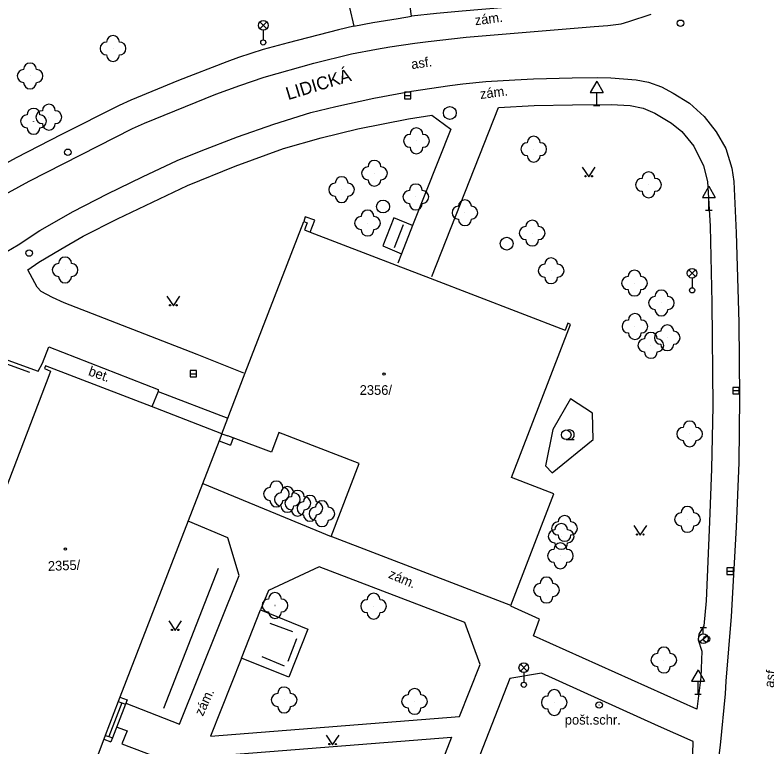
# Model space of a CAD drawing. Extents: x -737812 to -729375, y -1123000 to -1115500.
# Drawn here: x -736793.5 to -736735.1, y -1118373.1 to -1118316.3 of the extents above; entities that cross this region are included whole.
import ezdxf

# ---------------------------------------------------------------- set-up
doc = ezdxf.new("R2010")
doc.units = 0
for name, color, linetype in [('Doplněk polohopisu', 7, 'Continuous'), ('Doplňkové značky', 7, 'Continuous'), ('Hranice - ploty_ zdi', 7, 'Continuous'), ('Komunikace', 7, 'Continuous'), ('Názvy ulic_ silnic_ žel_', 7, 'Continuous'), ('Pomocné popisy', 7, 'Continuous'), ('Povr_ zn_ inž_ sítí - el_', 7, 'Continuous'), ('Povr_ zn_ inž_ sítí - kan_', 7, 'Continuous'), ('Povr_ zn_ inž_ sítí - vod_', 7, 'Continuous'), ('Stavební objekty', 7, 'Continuous'), ('Zeleň', 7, 'Continuous'), ('Značky druhů budov', 7, 'Continuous'), ('Značky druhů pozemků', 7, 'Continuous'), ('Čísla popisná', 7, 'Continuous')]:
    doc.layers.add(name, color=color, linetype=linetype)

msp = doc.modelspace()

# ---------------------------------------------------------------- linework, layer by layer
at = {"layer": 'Doplněk polohopisu'}
for p, q in [((-736763.36, -1118332.57), (-736764.06, -1118334.34)), ((-736762.64, -1118332.62), (-736763.5, -1118334.81)), ((-736782.39, -1118345.49), (-736776.98, -1118347.57)), ((-736778.92, -1118352.62), (-736768.95, -1118356.75)), ((-736775.92, -1118366.17), (-736774.44, -1118362.43)), ((-736773.71, -1118363.47), (-736771.94, -1118364.12)), ((-736771.64, -1118364.68), (-736772.31, -1118366.43)), ((-736772.58, -1118366.8), (-736774.31, -1118366.07))]:
    msp.add_line(p, q, dxfattribs=at)
for points in [[(-736744.93, -1118314.39), (-736745.88, -1118314.7), (-736746.86, -1118314.94), (-736758.79, -1118315.98), (-736760.78, -1118316.16), (-736762.72, -1118316.38), (-736762.93, -1118314.85), (-736764.64, -1118315.04), (-736767.54, -1118315.7), (-736767.2, -1118317.14), (-736768.39, -1118317.44), (-736772.3, -1118318.44), (-736774.22, -1118318.96), (-736776.13, -1118319.57), (-736777.06, -1118319.91), (-736780.81, -1118321.36), (-736784.51, -1118322.89), (-736785.41, -1118323.31), (-736789.87, -1118325.54), (-736793.41, -1118327.35), (-736795.73, -1118328.63), (-736798.16, -1118329.99), (-736802.42, -1118325.45), (-736793.42, -1118298.49)], [(-736767.2, -1118317.14), (-736765.72, -1118316.86), (-736763.76, -1118316.54), (-736762.72, -1118316.38)], [(-736761.15, -1118336.58), (-736755.97, -1118323.46), (-736753.2, -1118323.3), (-736750.21, -1118323.24), (-736747.22, -1118323.23), (-736745.74, -1118323.29), (-736744.73, -1118323.51), (-736743.84, -1118323.9), (-736742.55, -1118324.67), (-736741.74, -1118325.31), (-736740.8, -1118326.46), (-736740.06, -1118327.97), (-736739.74, -1118329.21), (-736739.54, -1118332.67), (-736739.41, -1118338.6), (-736739.32, -1118346.62), (-736739.43, -1118351.5), (-736739.58, -1118355.61), (-736739.84, -1118361.74), (-736740.02, -1118363.67), (-736740.42, -1118364.32), (-736740.47, -1118364.75), (-736740.19, -1118365.63), (-736740.27, -1118367.64), (-736740.56, -1118370.13), (-736753.24, -1118364.45), (-736752.77, -1118363.16), (-736755.02, -1118362.15)], [(-736775.74, -1118344.07), (-736779.35, -1118342.62), (-736789.66, -1118338.6), (-736790.58, -1118338.21), (-736791.45, -1118337.72), (-736791.77, -1118337.4), (-736792.49, -1118336.06), (-736791.63, -1118335.46), (-736789.92, -1118334.45), (-736788.19, -1118333.45), (-736785.54, -1118332.09), (-736782.82, -1118330.79), (-736780.1, -1118329.51), (-736776.39, -1118328.01), (-736772.66, -1118326.63), (-736769.73, -1118325.81), (-736766.87, -1118325.1), (-736762.96, -1118324.33), (-736761.14, -1118324.04), (-736759.66, -1118325.14), (-736762.64, -1118332.62)], [(-736762.64, -1118332.62), (-736764.1, -1118332.02), (-736764.94, -1118334.2), (-736763.5, -1118334.81)], [(-736763.5, -1118334.81), (-736763.77, -1118335.53)], [(-736797.29, -1118341.89), (-736791.7, -1118343.91)], [(-736784.88, -1118369.68), (-736780.71, -1118371.3), (-736776.09, -1118359.76), (-736776.98, -1118356.83), (-736780.06, -1118355.55)], [(-736778.32, -1118372.22), (-736758.99, -1118370.71), (-736757.4, -1118366.68), (-736758.59, -1118363.42), (-736769.87, -1118359.09), (-736773.82, -1118360.93), (-736774.44, -1118362.43)], [(-736785.55, -1118371.52), (-736784.79, -1118371.81), (-736785.19, -1118372.81), (-736781.77, -1118374.11), (-736785.16, -1118382.75), (-736787.08, -1118383.62), (-736808.59, -1118375.5), (-736809.93, -1118374.91), (-736808.63, -1118363.41), (-736808.27, -1118362.75), (-736807.61, -1118361.98), (-736807.24, -1118361.68), (-736806.73, -1118361.51), (-736806.23, -1118361.46), (-736805.75, -1118361.53), (-736801.56, -1118363.14), (-736800.31, -1118363.11)], [(-736774.44, -1118362.43), (-736770.76, -1118363.92), (-736772.23, -1118367.64), (-736775.92, -1118366.17), (-736778.32, -1118372.22)], [(-736764.62, -1118392.14), (-736762.99, -1118392.93), (-736748.6, -1118398.22), (-736745.09, -1118399.49), (-736744.75, -1118398.23), (-736744.01, -1118394.34), (-736745.6, -1118394), (-736744.54, -1118388.1), (-736743.62, -1118382.19), (-736742, -1118382.44), (-736740.89, -1118373.61), (-736740.85, -1118372.63), (-736743.56, -1118371.46), (-736752.63, -1118367.35), (-736755.08, -1118367.76), (-736764.62, -1118392.14)], [(-736778.95, -1118373.82), (-736759.6, -1118372.3), (-736766.41, -1118389.8), (-736768.59, -1118390.61), (-736781.95, -1118385.54), (-736782.77, -1118383.61), (-736778.95, -1118373.82)]]:
    msp.add_lwpolyline(points, dxfattribs=at)
at = {"layer": 'Doplňkové značky'}
for p, q in [((-736748.34, -1118321.424), (-736748.84, -1118322.29)), ((-736748.34, -1118321.424), (-736747.84, -1118322.29)), ((-736748.84, -1118322.29), (-736747.84, -1118322.29)), ((-736748.34, -1118323.29), (-736748.34, -1118322.29)), ((-736748.59, -1118323.29), (-736748.09, -1118323.29)), ((-736739.64, -1118329.564), (-736740.14, -1118330.43)), ((-736739.64, -1118329.564), (-736739.14, -1118330.43)), ((-736740.14, -1118330.43), (-736739.14, -1118330.43)), ((-736739.64, -1118331.43), (-736739.64, -1118330.43)), ((-736739.89, -1118331.43), (-736739.39, -1118331.43)), ((-736740.48, -1118367.094), (-736740.98, -1118367.96)), ((-736740.48, -1118367.094), (-736739.98, -1118367.96)), ((-736740.98, -1118367.96), (-736739.98, -1118367.96)), ((-736740.48, -1118368.96), (-736740.48, -1118367.96)), ((-736740.73, -1118368.96), (-736740.23, -1118368.96))]:
    msp.add_line(p, q, dxfattribs=at)
for radius in [0.25, 0.0005]:
    msp.add_circle((-736748.15, -1118369.81), radius, dxfattribs=at)
at = {"layer": 'Hranice - ploty_ zdi'}
for points in [[(-736770.98, -1118331.93), (-736771.07, -1118332.3)], [(-736770.22, -1118332.2), (-736770.98, -1118331.93)], [(-736770.57, -1118333.12), (-736770.22, -1118332.2)], [(-736791.7, -1118343.91), (-736791.36, -1118343.3), (-736790.86, -1118342.03), (-736782.37, -1118345.34), (-736782.39, -1118345.49), (-736782.87, -1118346.67)], [(-736796.54, -1118342.5), (-736792.36, -1118343.99)], [(-736777.64, -1118349.31), (-736776.77, -1118349.65)], [(-736776.56, -1118349.09), (-736776.77, -1118349.65)], [(-736781.94, -1118370.05), (-736777.69, -1118359.2)], [(-736785.34, -1118369.19), (-736784.78, -1118369.41)], [(-736784.78, -1118369.41), (-736784.91, -1118369.75)], [(-736785.2, -1118369.64), (-736786.21, -1118372.25)], [(-736784.91, -1118369.75), (-736785.92, -1118372.36)], [(-736785.47, -1118369.53), (-736785.2, -1118369.64), (-736784.91, -1118369.75)], [(-736786.49, -1118372.17), (-736786.21, -1118372.25), (-736785.92, -1118372.36)], [(-736785.92, -1118372.36), (-736786.05, -1118372.68)], [(-736786.6, -1118372.47), (-736786.05, -1118372.68)]]:
    msp.add_lwpolyline(points, dxfattribs=at)
at = {"layer": 'Komunikace'}
for points in [[(-736795.91, -1118331.09), (-736792.39, -1118329.17), (-736784.38, -1118325.09), (-736783.45, -1118324.68), (-736777.89, -1118322.43), (-736776.03, -1118321.74), (-736774.14, -1118321.11), (-736770.3, -1118320.03), (-736767.38, -1118319.3), (-736765.44, -1118318.92), (-736764.41, -1118318.76), (-736762.46, -1118318.47), (-736761.43, -1118318.33), (-736758.48, -1118318), (-736748.54, -1118317.18), (-736747.48, -1118317.1), (-736746.44, -1118316.96), (-736745.86, -1118316.78), (-736744.11, -1118316.21)], [(-736794.12, -1118334.63), (-736793.24, -1118334.1), (-736791.57, -1118332.99), (-736788.97, -1118331.53), (-736786.3, -1118330.15), (-736783.6, -1118328.84), (-736780.89, -1118327.57), (-736779.03, -1118326.81), (-736776.23, -1118325.73), (-736773.39, -1118324.74), (-736770.53, -1118323.85), (-736768.59, -1118323.39), (-736765.65, -1118322.74), (-736762.71, -1118322.19), (-736759.74, -1118321.75), (-736758.72, -1118321.63), (-736756.94, -1118321.45), (-736754.71, -1118321.3), (-736753.25, -1118321.23), (-736750.24, -1118321.15), (-736748.27, -1118321.14), (-736747.24, -1118321.16), (-736745.27, -1118321.32), (-736744.32, -1118321.49), (-736743.31, -1118321.86), (-736742.4, -1118322.34), (-736741.14, -1118323.12), (-736740, -1118324.15), (-736739.06, -1118325.35), (-736738.33, -1118326.64), (-736737.85, -1118328.17), (-736737.69, -1118329.19), (-736737.51, -1118333.17)], [(-736737.51, -1118333.17), (-736737.31, -1118340.14), (-736737.26, -1118345.98), (-736737.32, -1118351.01), (-736737.52, -1118356.02), (-736737.91, -1118362.94), (-736738.32, -1118367.96), (-736738.38, -1118368.94), (-736738.76, -1118372.93), (-736738.88, -1118373.94)]]:
    msp.add_lwpolyline(points, dxfattribs=at)
at = {"layer": 'Povr_ zn_ inž_ sítí - el_'}
for p, q in [((-736774.484, -1118317.348), (-736773.956, -1118316.82)), ((-736773.948, -1118317.345), (-736774.476, -1118316.816)), ((-736774.22, -1118317.46), (-736774.22, -1118318.21)), ((-736741.204, -1118336.578), (-736740.676, -1118336.05)), ((-736740.668, -1118336.575), (-736741.196, -1118336.046)), ((-736740.94, -1118336.69), (-736740.94, -1118337.44)), ((-736754.264, -1118367.178), (-736753.736, -1118366.65)), ((-736753.728, -1118367.175), (-736754.256, -1118366.646)), ((-736754, -1118367.29), (-736754, -1118368.04))]:
    msp.add_line(p, q, dxfattribs=at)
for centre, radius in [((-736774.22, -1118317.085), 0.375), ((-736774.22, -1118318.41), 0.2), ((-736740.94, -1118336.315), 0.375), ((-736740.94, -1118337.64), 0.2), ((-736754, -1118366.915), 0.375), ((-736754, -1118368.24), 0.2)]:
    msp.add_circle(centre, radius, dxfattribs=at)
at = {"layer": 'Povr_ zn_ inž_ sítí - kan_'}
for p, q in [((-736763.27, -1118322.53), (-736762.77, -1118322.53)), ((-736779.9, -1118344.11), (-736779.4, -1118344.11)), ((-736737.79, -1118345.42), (-736737.29, -1118345.42)), ((-736738.24, -1118359.43), (-736737.74, -1118359.43))]:
    msp.add_line(p, q, dxfattribs=at)
for points in [[(-736763.27, -1118322.781), (-736762.769, -1118322.781), (-736762.769, -1118322.279), (-736763.27, -1118322.279)], [(-736779.9, -1118344.361), (-736779.399, -1118344.361), (-736779.399, -1118343.859), (-736779.9, -1118343.859)], [(-736737.79, -1118345.671), (-736737.289, -1118345.671), (-736737.289, -1118345.169), (-736737.79, -1118345.169)], [(-736738.24, -1118359.681), (-736737.739, -1118359.681), (-736737.739, -1118359.179), (-736738.24, -1118359.179)]]:
    msp.add_lwpolyline(points, close=True, dxfattribs=at)
for centre in [(-736759.74, -1118323.88), (-736764.92, -1118331.14), (-736755.33, -1118334.02)]:
    msp.add_circle(centre, 0.5, dxfattribs=at)
at = {"layer": 'Povr_ zn_ inž_ sítí - vod_'}
for p, q in [((-736740.32, -1118363.795), (-736739.82, -1118363.795)), ((-736740.07, -1118364.295), (-736740.07, -1118363.795)), ((-736740.364, -1118364.901), (-736739.774, -1118364.438))]:
    msp.add_line(p, q, dxfattribs=at)
for centre, radius in [((-736741.84, -1118316.92), 0.25), ((-736789.39, -1118326.93), 0.25), ((-736792.39, -1118334.75), 0.25), ((-736740.07, -1118364.67), 0.375), ((-736739.81, -1118364.69), 0.25)]:
    msp.add_circle(centre, radius, dxfattribs=at)
at = {"layer": 'Stavební objekty'}
for points in [[(-736777.44, -1118348.77), (-736775.62, -1118344.03), (-736771.07, -1118332.3)], [(-736771.07, -1118332.3), (-736770.82, -1118332.4)], [(-736770.82, -1118332.4), (-736771.03, -1118332.94)], [(-736771.03, -1118332.94), (-736770.57, -1118333.12), (-736763.91, -1118335.68), (-736761.27, -1118336.7), (-736750.78, -1118340.72)], [(-736754.95, -1118352.16), (-736750.37, -1118340.28)], [(-736750.58, -1118340.19), (-736750.78, -1118340.72)], [(-736750.37, -1118340.28), (-736750.58, -1118340.19)], [(-736791.12, -1118343.5), (-736791.21, -1118343.71)], [(-736791.21, -1118343.71), (-736790.73, -1118343.91)], [(-736777.44, -1118348.77), (-736782.57, -1118346.79), (-736791.12, -1118343.5)], [(-736790.73, -1118343.91), (-736790.87, -1118344.27), (-736797.34, -1118361.13), (-736797.46, -1118361.44), (-736798.19, -1118363.37), (-736798.32, -1118363.7), (-736802.26, -1118373.97), (-736802.37, -1118374.26)], [(-736777.44, -1118348.77), (-736777.64, -1118349.31), (-736785.34, -1118369.19), (-736785.47, -1118369.53), (-736786.49, -1118372.17)], [(-736777.44, -1118348.77), (-736776.96, -1118348.94)], [(-736773.59, -1118350.2), (-736776.56, -1118349.09), (-736776.96, -1118348.94)], [(-736773, -1118348.66), (-736773.59, -1118350.2)], [(-736766.78, -1118351.07), (-736773, -1118348.66)], [(-736768.95, -1118356.75), (-736766.78, -1118351.07)], [(-736751.67, -1118353.42), (-736754.95, -1118352.16)], [(-736755.01, -1118362.09), (-736751.67, -1118353.42)], [(-736755.01, -1118362.09), (-736768.95, -1118356.75)], [(-736786.49, -1118372.17), (-736786.6, -1118372.47), (-736789.09, -1118379.04), (-736789.18, -1118379.28)]]:
    msp.add_lwpolyline(points, dxfattribs=at)
at = {"layer": 'Zeleň'}
for points in [[(-736750.38, -1118346.07), (-736751.75, -1118348.45)], [(-736748.68, -1118347.18), (-736750.38, -1118346.07)], [(-736748.61, -1118349.22), (-736748.68, -1118347.18)], [(-736751.75, -1118348.45), (-736752.31, -1118351.26)], [(-736751.81, -1118351.8), (-736748.61, -1118349.22)], [(-736752.31, -1118351.26), (-736751.81, -1118351.8)]]:
    msp.add_lwpolyline(points, dxfattribs=at)
for centre in [(-736785.88, -1118318.88), (-736792.32, -1118321.01), (-736792.05, -1118324.53), (-736790.86, -1118324.21), (-736762.33, -1118326.04), (-736753.23, -1118326.69), (-736765.59, -1118328.56), (-736744.32, -1118329.46), (-736768.14, -1118329.83), (-736762.38, -1118330.4), (-736758.57, -1118331.62), (-736766.13, -1118332.42), (-736753.35, -1118333.2), (-736789.6, -1118336.06), (-736751.88, -1118336.12), (-736745.41, -1118337.08), (-736743.32, -1118338.62), (-736745.38, -1118340.45), (-736742.87, -1118341.32), (-736744.14, -1118341.91), (-736741.13, -1118348.78), (-736773.2, -1118353.44), (-736772.35, -1118353.86), (-736771.54, -1118354.16), (-736770.6, -1118354.55), (-736769.67, -1118354.97), (-736741.3, -1118355.41), (-736750.84, -1118356.11), (-736751.1, -1118356.73), (-736751.16, -1118358.24), (-736752.24, -1118360.89), (-736773.31, -1118362.09), (-736765.66, -1118362.14), (-736743.13, -1118366.32), (-736772.6, -1118369.42), (-736762.48, -1118369.53), (-736751.64, -1118369.62)]:
    msp.add_circle(centre, 0.0005, dxfattribs=at)
for centre, start, end in [((-736785.88, -1118318.38), 360, 179.99999), ((-736786.38, -1118318.88), 89.99999, 269.99999), ((-736785.38, -1118318.88), 270, 89.99999), ((-736785.88, -1118319.38), 179.99999, 359.99999), ((-736792.32, -1118320.51), 360, 179.99999), ((-736792.82, -1118321.01), 89.99999, 269.99999), ((-736791.82, -1118321.01), 270, 89.99999), ((-736792.32, -1118321.51), 179.99999, 359.99999), ((-736790.86, -1118323.71), 360, 179.99999), ((-736792.05, -1118324.03), 360, 179.99999), ((-736791.36, -1118324.21), 89.99999, 269.99999), ((-736790.36, -1118324.21), 270, 89.99999), ((-736792.55, -1118324.53), 89.99999, 269.99999), ((-736791.55, -1118324.53), 270, 89.99999), ((-736792.05, -1118325.03), 179.99999, 359.99999), ((-736790.86, -1118324.71), 179.99999, 359.99999), ((-736762.33, -1118325.54), 360, 179.99999), ((-736762.83, -1118326.04), 89.99999, 269.99999), ((-736761.83, -1118326.04), 270, 89.99999), ((-736753.23, -1118326.19), 360, 179.99999), ((-736753.73, -1118326.69), 89.99999, 269.99999), ((-736752.73, -1118326.69), 270, 89.99999), ((-736762.33, -1118326.54), 179.99999, 359.99999), ((-736753.23, -1118327.19), 179.99999, 359.99999), ((-736765.59, -1118328.06), 360, 179.99999), ((-736766.09, -1118328.56), 89.99999, 269.99999), ((-736765.09, -1118328.56), 270, 89.99999), ((-736744.32, -1118328.96), 360, 179.99999), ((-736768.14, -1118329.33), 360, 179.99999), ((-736765.59, -1118329.06), 179.99999, 359.99999), ((-736744.82, -1118329.46), 89.99999, 269.99999), ((-736743.82, -1118329.46), 270, 89.99999), ((-736768.64, -1118329.83), 89.99999, 269.99999), ((-736767.64, -1118329.83), 270, 89.99999), ((-736762.38, -1118329.9), 360, 179.99999), ((-736768.14, -1118330.33), 179.99999, 359.99999), ((-736762.88, -1118330.4), 89.99999, 269.99999), ((-736761.88, -1118330.4), 270, 89.99999), ((-736744.32, -1118329.96), 179.99999, 359.99999), ((-736762.38, -1118330.9), 179.99999, 359.99999), ((-736758.57, -1118331.12), 360, 179.99999), ((-736766.13, -1118331.92), 360, 179.99999), ((-736759.07, -1118331.62), 89.99999, 269.99999), ((-736758.07, -1118331.62), 270, 89.99999), ((-736766.63, -1118332.42), 89.99999, 269.99999), ((-736765.63, -1118332.42), 270, 89.99999), ((-736758.57, -1118332.12), 179.99999, 359.99999), ((-736753.85, -1118333.2), 89.99999, 269.99999), ((-736753.35, -1118332.7), 360, 179.99999), ((-736752.85, -1118333.2), 270, 89.99999), ((-736766.13, -1118332.92), 179.99999, 359.99999), ((-736753.35, -1118333.7), 179.99999, 359.99999), ((-736789.6, -1118335.56), 0, 179.99999), ((-736790.1, -1118336.06), 89.99999, 269.99999), ((-736789.1, -1118336.06), 270, 89.99999), ((-736752.38, -1118336.12), 89.99999, 269.99999), ((-736751.88, -1118335.62), 360, 179.99999), ((-736751.38, -1118336.12), 270, 89.99999), ((-736745.41, -1118336.58), 360, 179.99999), ((-736789.6, -1118336.56), 179.99999, 359.99999), ((-736751.88, -1118336.62), 179.99999, 359.99999), ((-736745.91, -1118337.08), 89.99999, 269.99999), ((-736744.91, -1118337.08), 270, 89.99999), ((-736745.41, -1118337.58), 179.99999, 359.99999), ((-736743.32, -1118338.12), 360, 179.99999), ((-736743.82, -1118338.62), 89.99999, 269.99999), ((-736742.82, -1118338.62), 270, 89.99999), ((-736743.32, -1118339.12), 179.99999, 359.99999), ((-736745.38, -1118339.95), 360, 179.99999), ((-736745.88, -1118340.45), 89.99999, 269.99999), ((-736744.88, -1118340.45), 270, 89.99999), ((-736743.37, -1118341.32), 89.99999, 269.99999), ((-736742.87, -1118340.82), 360, 179.99999), ((-736742.37, -1118341.32), 270, 89.99999), ((-736745.38, -1118340.95), 179.99999, 359.99999), ((-736744.64, -1118341.91), 89.99999, 269.99999), ((-736744.14, -1118341.41), 360, 179.99999), ((-736743.64, -1118341.91), 270, 89.99999), ((-736742.87, -1118341.82), 179.99999, 359.99999), ((-736744.14, -1118342.41), 179.99999, 359.99999), ((-736741.13, -1118348.28), 0, 179.99999), ((-736741.63, -1118348.78), 89.99999, 269.99999), ((-736740.63, -1118348.78), 270, 89.99999), ((-736741.13, -1118349.28), 179.99999, 359.99999), ((-736773.2, -1118352.94), 360, 179.99999), ((-736773.7, -1118353.44), 89.99999, 269.99999), ((-736772.35, -1118353.36), 360, 179.99999), ((-736772.7, -1118353.44), 270, 89.99999), ((-736772.85, -1118353.86), 89.99999, 269.99999), ((-736772.04, -1118354.16), 89.99999, 269.99999), ((-736771.54, -1118353.66), 360, 179.99999), ((-736771.85, -1118353.86), 270, 89.99999), ((-736770.6, -1118354.05), 360, 179.99999), ((-736771.04, -1118354.16), 270, 89.99999), ((-736773.2, -1118353.94), 179.99999, 359.99999), ((-736771.1, -1118354.55), 89.99999, 269.99999), ((-736769.67, -1118354.47), 360, 179.99999), ((-736770.1, -1118354.55), 270, 89.99999), ((-736772.35, -1118354.36), 179.99999, 359.99999), ((-736771.54, -1118354.66), 179.99999, 359.99999), ((-736770.17, -1118354.97), 89.99999, 269.99999), ((-736769.17, -1118354.97), 270, 89.99999), ((-736741.3, -1118354.91), 0, 179.99999), ((-736770.6, -1118355.05), 179.99999, 359.99999), ((-736769.67, -1118355.47), 179.99999, 359.99999), ((-736750.84, -1118355.61), 360, 179.99999), ((-736741.8, -1118355.41), 89.99999, 269.99999), ((-736740.8, -1118355.41), 270, 89.99999), ((-736751.34, -1118356.11), 89.99999, 269.99999), ((-736751.1, -1118356.23), 360, 179.99999), ((-736750.34, -1118356.11), 270, 89.99999), ((-736741.3, -1118355.91), 179.99999, 359.99999), ((-736751.6, -1118356.73), 89.99999, 269.99999), ((-736750.84, -1118356.61), 179.99999, 359.99999), ((-736750.6, -1118356.73), 270, 89.99999), ((-736751.1, -1118357.23), 179.99999, 359.99999), ((-736751.66, -1118358.24), 89.99999, 269.99999), ((-736751.16, -1118357.74), 360, 179.99999), ((-736750.66, -1118358.24), 270, 89.99999), ((-736751.16, -1118358.74), 179.99999, 359.99999), ((-736752.24, -1118360.39), 360, 179.99999), ((-736752.74, -1118360.89), 89.99999, 269.99999), ((-736751.74, -1118360.89), 270, 89.99999), ((-736773.31, -1118361.59), 360, 179.99999), ((-736765.66, -1118361.64), 360, 179.99999), ((-736773.81, -1118362.09), 89.99999, 269.99999), ((-736772.81, -1118362.09), 270, 89.99999), ((-736766.16, -1118362.14), 89.99999, 269.99999), ((-736765.16, -1118362.14), 270, 89.99999), ((-736752.24, -1118361.39), 179.99999, 359.99999), ((-736773.31, -1118362.59), 179.99999, 359.99999), ((-736765.66, -1118362.64), 179.99999, 359.99999), ((-736743.13, -1118365.82), 0, 179.99999), ((-736743.63, -1118366.32), 89.99999, 269.99999), ((-736742.63, -1118366.32), 270, 89.99999), ((-736743.13, -1118366.82), 179.99999, 359.99999), ((-736772.6, -1118368.92), 360, 179.99999), ((-736762.48, -1118369.03), 360, 179.99999), ((-736751.64, -1118369.12), 360, 179.99999), ((-736773.1, -1118369.42), 89.99999, 269.99999), ((-736772.1, -1118369.42), 270, 89.99999), ((-736762.98, -1118369.53), 89.99999, 269.99999), ((-736761.98, -1118369.53), 270, 89.99999), ((-736752.14, -1118369.62), 89.99999, 269.99999), ((-736751.14, -1118369.62), 270, 89.99999), ((-736772.6, -1118369.92), 179.99999, 359.99999), ((-736762.48, -1118370.03), 179.99999, 359.99999), ((-736751.64, -1118370.12), 179.99999, 359.99999)]:
    msp.add_arc(centre, 0.5, start, end, dxfattribs=at)
at = {"layer": 'Značky druhů budov'}
for centre in [(-736764.85, -1118344.139), (-736789.58, -1118357.709)]:
    msp.add_circle(centre, 0.0875, dxfattribs=at)
at = {"layer": 'Značky druhů pozemků'}
msp.add_line((-736750.71, -1118349.225), (-736750.085, -1118349.225), dxfattribs=at)
for points in [[(-736749.46, -1118328.09), (-736748.96, -1118328.84), (-736748.46, -1118328.09)], [(-736781.7, -1118338.1), (-736781.2, -1118338.85), (-736780.7, -1118338.1)], [(-736745.46, -1118355.88), (-736744.96, -1118356.63), (-736744.46, -1118355.88)], [(-736781.56, -1118363.29), (-736781.06, -1118364.04), (-736780.56, -1118363.29)], [(-736769.34, -1118372.14), (-736768.84, -1118372.89), (-736768.34, -1118372.14)]]:
    msp.add_lwpolyline(points, dxfattribs=at)
for centre, radius in [((-736749.21, -1118328.79), 0.05), ((-736748.71, -1118328.79), 0.05), ((-736781.45, -1118338.8), 0.05), ((-736780.95, -1118338.8), 0.05), ((-736750.71, -1118348.85), 0.375), ((-736745.21, -1118356.58), 0.05), ((-736744.71, -1118356.58), 0.05), ((-736781.31, -1118363.99), 0.05), ((-736780.81, -1118363.99), 0.05), ((-736769.089, -1118372.84), 0.05), ((-736768.589, -1118372.84), 0.05)]:
    msp.add_circle(centre, radius, dxfattribs=at)
msp.add_arc((-736750.46, -1118348.85), 0.375, 249.49437, 109.04743, dxfattribs=at)

# ---------------------------------------------------------------- texts
at = {"layer": 'Názvy ulic_ silnic_ žel_'}
msp.add_text('LIDICKÁ', height=1, rotation=16.92486, dxfattribs=at).set_placement((-736772.29, -1118322.89))
at = {"layer": 'Pomocné popisy'}
for s, rotation, p in [('zám.', 7.32841, (-736757.76, -1118317.08)), ('asf.', 8.02829, (-736762.69, -1118320.48)), ('zám.', 7.32841, (-736757.36, -1118322.8)), ('bet.', 340.45642, (-736787.85, -1118344.21)), ('zám.', 336.69163, (-736764.57, -1118359.92)), ('asf.', 82.08641, (-736734.61, -1118368.5)), ('zám.', 65.37523, (-736778.91, -1118370.73))]:
    msp.add_text(s, height=0.75, rotation=rotation, dxfattribs=at).set_placement(p)
msp.add_text('pošt.schr.', height=0.75, dxfattribs=at).set_placement((-736750.82, -1118371.33))
at = {"layer": 'Čísla popisná'}
msp.add_text('2356/', height=0.75, dxfattribs=at).set_placement((-736766.74, -1118345.75))
msp.add_text('2355/', height=0.75, rotation=2.26173, dxfattribs=at).set_placement((-736790.92, -1118359.41))

doc.saveas('drawing.dxf')
